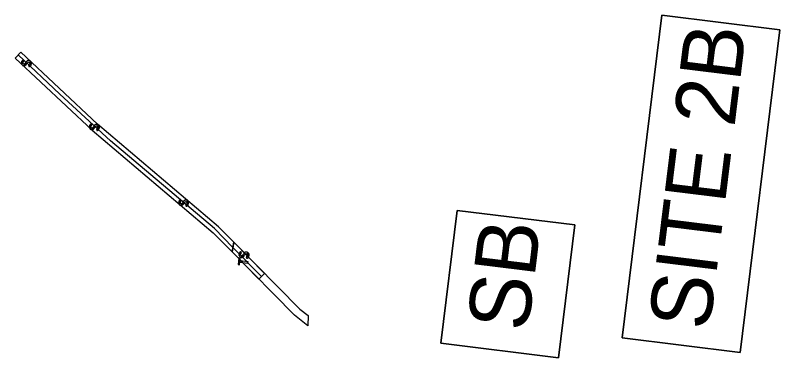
# Model space of a CAD drawing. Extents: x 474218 to 481634, y 484357 to 504997.
# Drawn here: x 481446.4 to 481633.6, y 491316.6 to 491400.4 of the extents above; entities that cross this region are included whole.
import ezdxf

# ---------------------------------------------------------------- set-up
doc = ezdxf.new("R2010")
doc.units = 0
for name, color, linetype in [('Exist Hydro Jurisdictional Stream or Body of Water', 7, 'Continuous'), ('Old_Level_29', 7, 'Continuous'), ('Prop Earthen Structure Impacts In Surface Waters Hatching CELL', 7, 'Continuous'), ('Prop Grid Mask', 7, 'Continuous'), ('Scratch_Level_4', 7, 'Continuous'), ('Temp Earthen Structure Impacts In Surface Waters Hatching CELL', 7, 'Continuous')]:
    doc.layers.add(name, color=color, linetype=linetype)

msp = doc.modelspace()

# ---------------------------------------------------------------- linework, layer by layer
at = {"layer": 'Exist Hydro Jurisdictional Stream or Body of Water'}
msp.add_lwpolyline([(481550.57, 491320.15), (481554.57, 491352.67), (481583.44, 491349.12), (481579.43, 491316.6)], close=True, dxfattribs=at)
at = {"layer": 'Old_Level_29'}
msp.add_lwpolyline([(481594.99, 491321.46), (481604.71, 491400.43), (481633.58, 491396.88), (481623.86, 491317.91)], close=True, dxfattribs=at)
at = {"layer": 'Prop Earthen Structure Impacts In Surface Waters Hatching CELL'}
msp.add_lwpolyline([(481446.35, 491389.96), (481465.15, 491372.29), (481494.79, 491347.2), (481499.44, 491342.48), (481499.92, 491344.85), (481496.15, 491348.67), (481466.48, 491373.78), (481447.72, 491391.42), (481446.35, 491389.96)], dxfattribs=at)
for points in [[(481447.87, 491388.61), (481447.88, 491388.58), (481447.95, 491389.16), (481447.94, 491389.15), (481447.87, 491388.87), (481447.87, 491388.87)], [(481448.48, 491388.09), (481448.57, 491388.08), (481448.63, 491388.52), (481448.53, 491388.48), (481448.4, 491388.49), (481448.4, 491388.49), (481448.37, 491388.51), (481448.29, 491388.55), (481448.26, 491388.59), (481448.23, 491388.64), (481448.21, 491388.66), (481448.21, 491388.68), (481448.2, 491388.74), (481448.19, 491388.82), (481448.28, 491389.46), (481448.24, 491389.45), (481448.11, 491389.36), (481448.08, 491389.34), (481447.95, 491389.16), (481447.88, 491388.58), (481447.95, 491388.39), (481447.97, 491388.35), (481448.08, 491388.24), (481448.12, 491388.21), (481448.13, 491388.19), (481448.15, 491388.18), (481448.15, 491388.18), (481448.17, 491388.17), (481448.21, 491388.15), (481448.23, 491388.14), (481448.32, 491388.11), (481448.34, 491388.1), (481448.35, 491388.1)], [(481448.36, 491389.11), (481448.45, 491389.17), (481448.39, 491389.34), (481448.37, 491389.4), (481448.34, 491389.48), (481448.32, 491389.48), (481448.31, 491389.48), (481448.3, 491389.47), (481448.28, 491389.46), (481448.19, 491388.82), (481448.23, 491388.98), (481448.25, 491389), (481448.26, 491389.01), (481448.28, 491389.04), (481448.33, 491389.09)], [(481448.72, 491388.13), (481448.77, 491388.15), (481448.85, 491388.77), (481448.79, 491388.67), (481448.67, 491388.54), (481448.63, 491388.52), (481448.57, 491388.08), (481448.61, 491388.1)], [(481449.95, 491388.73), (481449.95, 491388.58), (481450.04, 491389.23), (481450.02, 491389.25), (481450.01, 491389.25), (481450.01, 491389.26), (481449.97, 491389.29), (481449.95, 491389.3), (481449.93, 491389.3), (481449.87, 491389.33), (481449.84, 491389.34), (481449.82, 491389.35), (481449.73, 491389.38), (481449.68, 491389.38), (481449.54, 491389.38), (481449.48, 491389.38), (481449.44, 491389.36), (481449.34, 491389.32), (481449.34, 491389.32), (481449.26, 491389.29), (481449.21, 491389.24), (481449.08, 491389.11), (481449.05, 491389.07), (481448.91, 491388.87), (481448.85, 491388.77), (481448.77, 491388.15), (481448.83, 491388.19), (481448.95, 491388.28), (481448.98, 491388.32), (481449.12, 491388.5), (481449.17, 491388.59), (481449.26, 491388.72), (481449.37, 491388.88), (481449.42, 491388.92), (481449.49, 491388.97), (481449.63, 491389), (481449.68, 491388.98), (481449.77, 491388.96), (481449.79, 491388.95), (481449.82, 491388.93), (481449.88, 491388.88), (481449.89, 491388.86), (481449.91, 491388.83), (481449.94, 491388.75), (481449.95, 491388.74)], [(481450.21, 491388.21), (481450.3, 491388.52), (481450.29, 491388.86), (481450.29, 491388.86), (481450.17, 491389.1), (481450.16, 491389.13), (481450.04, 491389.23), (481449.95, 491388.58), (481449.91, 491388.41), (481449.9, 491388.41), (481449.9, 491388.4), (481449.84, 491388.31), (481449.82, 491388.28), (481449.8, 491388.27), (481449.73, 491388.22), (481449.69, 491388.2), (481449.67, 491388.2), (481449.58, 491388.18), (481449.64, 491387.98), (481449.66, 491387.92), (481449.68, 491387.86), (481449.75, 491387.87), (481449.76, 491387.87), (481449.78, 491387.88), (481449.83, 491387.89), (481449.84, 491387.89), (481449.84, 491387.89), (481449.87, 491387.9), (481450.01, 491387.98), (481450.03, 491387.99), (481450.2, 491388.2)], [(481465.13, 491372.44), (481465.22, 491372.43), (481465.28, 491372.87), (481465.18, 491372.83), (481465.05, 491372.84), (481465.04, 491372.84), (481465.01, 491372.86), (481464.93, 491372.9), (481464.91, 491372.94), (481464.88, 491372.99), (481464.86, 491373.01), (481464.86, 491373.03), (481464.85, 491373.09), (481464.84, 491373.17), (481464.93, 491373.82), (481464.88, 491373.8), (481464.75, 491373.71), (481464.72, 491373.69), (481464.6, 491373.51), (481464.52, 491372.93), (481464.6, 491372.75), (481464.62, 491372.7), (481464.73, 491372.59), (481464.76, 491372.56), (481464.78, 491372.54), (481464.8, 491372.53), (481464.8, 491372.53), (481464.82, 491372.52), (481464.85, 491372.51), (481464.88, 491372.49), (481464.96, 491372.46), (481464.99, 491372.45), (481465, 491372.45)], [(481464.52, 491372.96), (481464.52, 491372.93), (481464.6, 491373.51), (481464.59, 491373.5), (481464.52, 491373.22), (481464.52, 491373.22)], [(481465.01, 491373.46), (481465.1, 491373.52), (481465.04, 491373.69), (481465.02, 491373.75), (481464.99, 491373.83), (481464.97, 491373.83), (481464.96, 491373.83), (481464.95, 491373.82), (481464.93, 491373.82), (481464.84, 491373.17), (481464.88, 491373.33), (481464.9, 491373.35), (481464.91, 491373.36), (481464.93, 491373.39), (481464.98, 491373.45)], [(481466.6, 491373.08), (481466.6, 491372.93), (481466.69, 491373.58), (481466.66, 491373.6), (481466.66, 491373.6), (481466.66, 491373.61), (481466.61, 491373.64), (481466.6, 491373.65), (481466.58, 491373.66), (481466.52, 491373.68), (481466.49, 491373.69), (481466.47, 491373.7), (481466.38, 491373.73), (481466.32, 491373.73), (481466.19, 491373.73), (481466.13, 491373.73), (481466.08, 491373.71), (481465.99, 491373.67), (481465.99, 491373.67), (481465.91, 491373.64), (481465.86, 491373.59), (481465.73, 491373.46), (481465.7, 491373.42), (481465.56, 491373.22), (481465.5, 491373.12), (481465.42, 491372.5), (481465.48, 491372.54), (481465.6, 491372.63), (481465.63, 491372.67), (481465.76, 491372.85), (481465.82, 491372.94), (481465.91, 491373.07), (481466.02, 491373.23), (481466.07, 491373.27), (481466.14, 491373.32), (481466.27, 491373.35), (481466.33, 491373.33), (481466.42, 491373.31), (481466.44, 491373.3), (481466.46, 491373.28), (481466.53, 491373.23), (481466.54, 491373.21), (481466.55, 491373.18), (481466.59, 491373.1), (481466.6, 491373.09)], [(481466.85, 491372.56), (481466.95, 491372.87), (481466.94, 491373.21), (481466.94, 491373.21), (481466.82, 491373.45), (481466.81, 491373.48), (481466.69, 491373.58), (481466.6, 491372.93), (481466.56, 491372.76), (481466.55, 491372.76), (481466.55, 491372.75), (481466.49, 491372.66), (481466.47, 491372.63), (481466.45, 491372.62), (481466.37, 491372.57), (481466.34, 491372.55), (481466.32, 491372.55), (481466.23, 491372.53), (481466.29, 491372.33), (481466.31, 491372.27), (481466.33, 491372.21), (481466.4, 491372.22), (481466.41, 491372.22), (481466.43, 491372.23), (481466.48, 491372.24), (481466.49, 491372.24), (481466.49, 491372.24), (481466.52, 491372.26), (481466.66, 491372.33), (481466.68, 491372.34), (481466.85, 491372.55)], [(481465.37, 491372.48), (481465.42, 491372.5), (481465.5, 491373.12), (481465.44, 491373.02), (481465.32, 491372.89), (481465.28, 491372.87), (481465.22, 491372.43), (481465.26, 491372.45)], [(481486.99, 491353.9), (481487.08, 491353.89), (481487.14, 491354.33), (481487.04, 491354.29), (481486.91, 491354.3), (481486.91, 491354.3), (481486.88, 491354.32), (481486.8, 491354.36), (481486.77, 491354.4), (481486.74, 491354.45), (481486.72, 491354.47), (481486.72, 491354.49), (481486.71, 491354.55), (481486.7, 491354.63), (481486.79, 491355.27), (481486.74, 491355.26), (481486.62, 491355.17), (481486.59, 491355.15), (481486.46, 491354.97), (481486.38, 491354.39), (481486.46, 491354.2), (481486.48, 491354.15), (481486.59, 491354.05), (481486.63, 491354.02), (481486.64, 491354), (481486.66, 491353.99), (481486.66, 491353.99), (481486.68, 491353.98), (481486.72, 491353.96), (481486.74, 491353.95), (481486.82, 491353.92), (481486.85, 491353.91), (481486.86, 491353.91)], [(481486.38, 491354.42), (481486.38, 491354.39), (481486.46, 491354.97), (481486.45, 491354.96), (481486.38, 491354.68), (481486.38, 491354.67)], [(481486.87, 491354.92), (481486.96, 491354.98), (481486.9, 491355.15), (481486.88, 491355.21), (481486.85, 491355.29), (481486.83, 491355.29), (481486.82, 491355.29), (481486.81, 491355.28), (481486.79, 491355.27), (481486.7, 491354.63), (481486.74, 491354.79), (481486.76, 491354.81), (481486.77, 491354.82), (481486.79, 491354.85), (481486.84, 491354.9)], [(481488.46, 491354.54), (481488.46, 491354.39), (481488.55, 491355.04), (481488.52, 491355.06), (481488.52, 491355.06), (481488.52, 491355.07), (481488.48, 491355.1), (481488.46, 491355.11), (481488.44, 491355.11), (481488.38, 491355.14), (481488.35, 491355.15), (481488.33, 491355.16), (481488.24, 491355.19), (481488.19, 491355.19), (481488.05, 491355.19), (481487.99, 491355.19), (481487.94, 491355.17), (481487.85, 491355.13), (481487.85, 491355.13), (481487.77, 491355.1), (481487.72, 491355.05), (481487.59, 491354.92), (481487.56, 491354.88), (481487.42, 491354.68), (481487.36, 491354.58), (481487.28, 491353.96), (481487.34, 491354), (481487.46, 491354.09), (481487.49, 491354.13), (481487.63, 491354.31), (481487.68, 491354.4), (481487.77, 491354.53), (481487.88, 491354.69), (481487.93, 491354.73), (481488, 491354.78), (481488.14, 491354.81), (481488.19, 491354.79), (481488.28, 491354.77), (481488.3, 491354.76), (481488.33, 491354.74), (481488.39, 491354.69), (481488.4, 491354.67), (481488.42, 491354.64), (481488.45, 491354.56), (481488.46, 491354.55)], [(481488.72, 491354.02), (481488.81, 491354.33), (481488.8, 491354.67), (481488.8, 491354.67), (481488.68, 491354.91), (481488.67, 491354.94), (481488.55, 491355.04), (481488.46, 491354.39), (481488.42, 491354.22), (481488.41, 491354.22), (481488.41, 491354.21), (481488.35, 491354.12), (481488.33, 491354.09), (481488.31, 491354.08), (481488.24, 491354.03), (481488.2, 491354.01), (481488.18, 491354.01), (481488.09, 491353.98), (481488.15, 491353.79), (481488.17, 491353.73), (481488.19, 491353.67), (481488.26, 491353.68), (481488.27, 491353.68), (481488.29, 491353.69), (481488.34, 491353.7), (481488.35, 491353.7), (481488.35, 491353.7), (481488.38, 491353.71), (481488.52, 491353.79), (481488.54, 491353.8), (481488.71, 491354.01)], [(481487.23, 491353.94), (481487.28, 491353.96), (481487.36, 491354.58), (481487.3, 491354.47), (481487.18, 491354.35), (481487.14, 491354.33), (481487.08, 491353.89), (481487.12, 491353.91)]]:
    msp.add_lwpolyline(points, close=True, dxfattribs=at)
at = {"layer": 'Prop Grid Mask'}
for points in [[(481623.86, 491317.91), (481633.58, 491396.88), (481604.71, 491400.43), (481594.99, 491321.46)], [(481579.43, 491316.6), (481583.44, 491349.12), (481554.57, 491352.67), (481550.57, 491320.15)]]:
    msp.add_lwpolyline(points, close=True, dxfattribs=at)
at = {"layer": 'Scratch_Level_4'}
for points in [[(481499.44, 491342.48), (481499.92, 491344.85), (481496.15, 491348.67), (481466.48, 491373.78), (481447.72, 491391.42), (481446.35, 491389.96), (481465.15, 491372.29), (481494.79, 491347.2)], [(481446.35, 491389.96), (481465.15, 491372.29), (481494.79, 491347.2), (481499.44, 491342.48), (481499.92, 491344.85), (481496.15, 491348.67), (481466.48, 491373.78), (481447.72, 491391.42)], [(481499.44, 491342.48), (481499.92, 491344.85), (481516.07, 491328.48), (481518.07, 491326.9), (481517.99, 491324.42), (481514.73, 491326.99)]]:
    msp.add_lwpolyline(points, close=True, dxfattribs=at)
for points in [[(481499.66, 491343.6), (481495.12, 491348.23), (481469.68, 491369.68), (481457.23, 491381.14), (481447.07, 491390.73)], [(481506.65, 491336.46), (481499.66, 491343.6)]]:
    msp.add_lwpolyline(points, dxfattribs=at)
at = {"layer": 'Temp Earthen Structure Impacts In Surface Waters Hatching CELL'}
msp.add_lwpolyline([(481499.44, 491342.48), (481506.02, 491335.82), (481506.02, 491335.82), (481507.42, 491337.24), (481507.42, 491337.24), (481499.92, 491344.85), (481499.44, 491342.48)], dxfattribs=at)
for points in [[(481501.19, 491341.68), (481501.2, 491341.65), (481501.27, 491342.23), (481501.26, 491342.22), (481501.19, 491341.94), (481501.19, 491341.94)], [(481501.81, 491341.16), (481501.89, 491341.16), (481501.95, 491341.6), (481501.86, 491341.56), (481501.73, 491341.57), (481501.72, 491341.57), (481501.69, 491341.58), (481501.61, 491341.62), (481501.58, 491341.66), (481501.55, 491341.71), (481501.53, 491341.74), (481501.53, 491341.75), (481501.52, 491341.81), (481501.51, 491341.89), (481501.59, 491342.54), (481501.55, 491342.52), (481501.42, 491342.43), (481501.39, 491342.41), (481501.27, 491342.23), (481501.2, 491341.65), (481501.28, 491341.47), (481501.3, 491341.42), (481501.4, 491341.32), (481501.44, 491341.28), (481501.46, 491341.26), (481501.47, 491341.25), (481501.47, 491341.25), (481501.49, 491341.24), (481501.53, 491341.23), (481501.56, 491341.22), (481501.64, 491341.18), (481501.67, 491341.17), (481501.68, 491341.17)], [(481501.68, 491342.19), (481501.77, 491342.24), (481501.7, 491342.42), (481501.68, 491342.48), (481501.65, 491342.56), (481501.63, 491342.55), (481501.63, 491342.55), (481501.61, 491342.54), (481501.59, 491342.54), (481501.51, 491341.89), (481501.55, 491342.05), (481501.57, 491342.08), (481501.58, 491342.08), (481501.6, 491342.11), (481501.64, 491342.17)], [(481502.04, 491341.21), (481502.09, 491341.23), (481502.17, 491341.85), (481502.11, 491341.74), (481501.99, 491341.62), (481501.95, 491341.6), (481501.89, 491341.16), (481501.93, 491341.17)], [(481503.27, 491341.82), (481503.27, 491341.67), (481503.35, 491342.32), (481503.33, 491342.34), (481503.33, 491342.34), (481503.32, 491342.34), (481503.28, 491342.38), (481503.26, 491342.38), (481503.25, 491342.39), (481503.18, 491342.41), (481503.15, 491342.42), (481503.13, 491342.43), (481503.05, 491342.46), (481502.99, 491342.46), (481502.86, 491342.46), (481502.8, 491342.46), (481502.75, 491342.44), (481502.66, 491342.4), (481502.66, 491342.4), (481502.58, 491342.37), (481502.53, 491342.32), (481502.4, 491342.19), (481502.37, 491342.14), (481502.23, 491341.95), (481502.17, 491341.85), (481502.09, 491341.22), (481502.15, 491341.27), (481502.27, 491341.36), (481502.3, 491341.4), (481502.44, 491341.58), (481502.49, 491341.67), (481502.58, 491341.8), (481502.69, 491341.96), (481502.74, 491342), (481502.81, 491342.05), (481502.94, 491342.08), (481503, 491342.06), (481503.08, 491342.04), (481503.11, 491342.03), (481503.13, 491342.01), (481503.2, 491341.97), (481503.21, 491341.94), (481503.22, 491341.91), (481503.26, 491341.83), (481503.27, 491341.83)], [(481503.53, 491341.29), (481503.62, 491341.61), (481503.61, 491341.94), (481503.61, 491341.95), (481503.49, 491342.19), (481503.48, 491342.21), (481503.35, 491342.32), (481503.27, 491341.67), (481503.23, 491341.49), (481503.23, 491341.49), (481503.22, 491341.48), (481503.16, 491341.4), (481503.14, 491341.37), (481503.12, 491341.36), (481503.05, 491341.31), (481503.02, 491341.29), (481502.99, 491341.28), (481502.9, 491341.26), (481502.96, 491341.06), (481502.98, 491341.01), (481503, 491340.94), (481503.07, 491340.95), (481503.09, 491340.96), (481503.11, 491340.96), (481503.16, 491340.97), (481503.16, 491340.97), (481503.16, 491340.97), (481503.19, 491340.99), (481503.34, 491341.07), (481503.36, 491341.08), (481503.53, 491341.29)], [(481500.93, 491339.4), (481501.25, 491339.36), (481501.45, 491340.97), (481501.13, 491341.01)], [(481501.33, 491339.98), (481503.33, 491339.73), (481503.37, 491340.11), (481501.37, 491340.35)]]:
    msp.add_lwpolyline(points, close=True, dxfattribs=at)

# ---------------------------------------------------------------- texts
at = {"layer": 'Exist Hydro Jurisdictional Stream or Body of Water'}
msp.add_text('SB', height=15, rotation=82.9799, dxfattribs=at).set_placement((481571.87, 491322.72))
at = {"layer": 'Old_Level_29'}
msp.add_text('SITE 2B', height=15, rotation=82.9799, dxfattribs=at).set_placement((481616.34, 491323.05))

doc.saveas('drawing.dxf')
